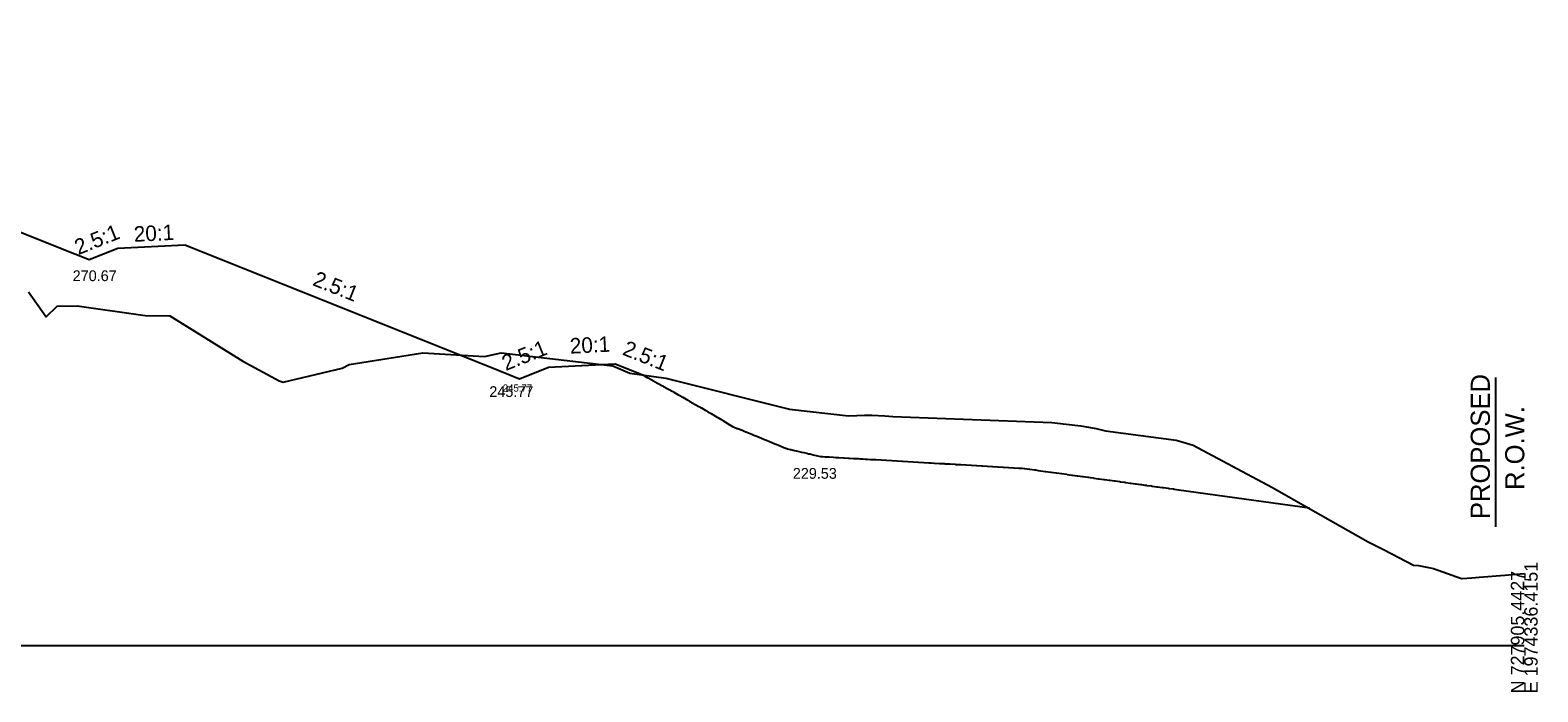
# Model space of a CAD drawing. Extents: x -26 to 1604, y -13 to 9623.
# Drawn here: x 287.7 to 602.8, y 7990.3 to 8128.6 of the extents above; entities that cross this region are included whole.
import ezdxf

# ---------------------------------------------------------------- set-up
doc = ezdxf.new("R2010")
doc.units = 0
for name, color, linetype in [('Default', 7, 'Continuous'), ('DTM CONTOURS_MAJOR', 7, 'Continuous'), ('DTM_X_GROUND', 7, 'Continuous'), ('SLOPE_STAKES_FILL', 7, 'Continuous'), ('XS_CELL', 7, 'Continuous'), ('XS_P_GROUND', 7, 'Continuous'), ('XS_P_ROW', 7, 'Continuous'), ('XS_P_TX_DCH', 7, 'Continuous'), ('XS_P_TX_FS_BS', 7, 'Continuous')]:
    doc.layers.add(name, color=color, linetype=linetype)

msp = doc.modelspace()

# ---------------------------------------------------------------- linework, layer by layer
at = {"layer": 'DTM_X_GROUND'}
msp.add_lwpolyline([(287.31, 8073.96), (291.04, 8068.73), (293.33, 8070.97), (297.48, 8071.01), (311.74, 8069), (316.85, 8068.91), (332.12, 8059.44), (339.7, 8055.36), (340.59, 8055.06), (352.88, 8058), (354.33, 8058.72), (369.76, 8061.16), (382.67, 8060.4), (386.12, 8061.2), (409.46, 8058.49), (413.06, 8056.92), (420.55, 8055.91), (446.41, 8049.38), (458.74, 8048.02), (460.47, 8048.07), (462.11, 8048.12), (463.65, 8048.17), (466.33, 8048.04), (467.98, 8047.87), (501.28, 8046.61), (504.23, 8046.28), (507.3, 8045.94), (510.52, 8045.36), (512.48, 8044.84), (527.24, 8042.93), (528.73, 8042.5), (530.82, 8041.91), (547.21, 8033.07), (557.38, 8027.32), (567.35, 8021.68), (570.73, 8019.99), (576.84, 8016.82), (577.91, 8016.74), (581.02, 8016.08), (586.91, 8013.97), (587.03, 8013.99), (589.06, 8014.17), (590.54, 8014.28), (595.97, 8014.73), (596.71, 8014.79), (600, 8015.02)], dxfattribs=at)
at = {"layer": 'XS_CELL'}
msp.add_line((100, 8000), (600, 8000), dxfattribs=at)
at = {"layer": 'XS_P_GROUND'}
for points in [[(142, 8128.64), (204, 8107.97), (210, 8105.97), (216, 8107.97), (230, 8108.67), (294, 8083.07), (300, 8080.67), (306, 8083.07), (320, 8083.77), (384, 8058.17), (390, 8055.77), (396, 8058.17), (410, 8058.87), (415.78, 8056.56)], [(415.78, 8056.56), (416.05, 8056.37), (416.06, 8056.37), (416.68, 8056.03), (416.71, 8056.01), (417.74, 8055.45), (417.82, 8055.4), (418.81, 8054.86), (418.93, 8054.79), (419.88, 8054.26), (420.04, 8054.17), (420.95, 8053.67), (421.15, 8053.55), (422.01, 8053.08), (422.26, 8052.93), (423.07, 8052.48), (423.37, 8052.3), (424.13, 8051.89), (424.48, 8051.68), (425.18, 8051.29), (425.59, 8051.04), (426.23, 8050.69), (426.71, 8050.41), (427.62, 8049.88), (427.82, 8049.77), (427.98, 8049.67), (427.99, 8049.67), (428.93, 8049.12), (429.37, 8048.87), (430.04, 8048.47), (430.4, 8048.27), (431.15, 8047.81), (431.43, 8047.65), (432.26, 8047.15), (432.45, 8047.04), (433.37, 8046.48), (433.47, 8046.42), (434.48, 8045.8), (434.48, 8045.8), (434.48, 8045.8), (435.47, 8045.39), (435.59, 8045.35), (436.48, 8044.99), (436.7, 8044.89), (437.49, 8044.57), (437.81, 8044.44), (437.82, 8044.44), (437.82, 8044.44), (438.52, 8044.15), (438.92, 8043.99), (439.55, 8043.74), (440.04, 8043.54), (440.56, 8043.33), (441.15, 8043.09), (441.57, 8042.91), (442.26, 8042.64), (442.58, 8042.5), (443.37, 8042.18), (443.6, 8042.09), (444.48, 8041.73), (444.61, 8041.68), (445.59, 8041.28), (445.62, 8041.27), (445.96, 8041.13)], [(445.96, 8041.13), (446.54, 8040.99), (446.7, 8040.96), (447.46, 8040.78), (447.81, 8040.7), (448.42, 8040.56), (448.92, 8040.44), (449.4, 8040.33), (450.03, 8040.18), (450.4, 8040.1), (450.65, 8040.04), (451.14, 8039.92), (451.38, 8039.87), (452.25, 8039.67), (452.86, 8039.53), (453.1, 8039.51), (453.36, 8039.5), (453.83, 8039.47), (454.48, 8039.43), (454.7, 8039.42), (455.59, 8039.37), (455.64, 8039.36), (456.14, 8039.33), (456.44, 8039.32), (456.45, 8039.32), (456.69, 8039.3), (456.7, 8039.3), (457.71, 8039.24), (457.81, 8039.24), (458.75, 8039.18), (458.92, 8039.17), (459.77, 8039.12), (460.03, 8039.11), (460.77, 8039.06), (461.14, 8039.04), (461.75, 8039.01), (462.25, 8038.98), (462.7, 8038.95), (463.36, 8038.91), (463.6, 8038.9), (464.34, 8038.85), (464.47, 8038.85), (464.47, 8038.85), (465.58, 8038.78), (465.59, 8038.78), (466.67, 8038.72), (466.67, 8038.72), (466.69, 8038.72), (466.71, 8038.72), (467.8, 8038.65), (467.82, 8038.65), (468.92, 8038.59), (468.94, 8038.59), (470.03, 8038.52), (470.06, 8038.52), (471.14, 8038.46), (471.17, 8038.46), (472.25, 8038.39), (472.28, 8038.39), (473.36, 8038.33), (473.4, 8038.33), (474.47, 8038.26), (475.54, 8038.2), (475.58, 8038.2), (476.02, 8038.17), (476.04, 8038.17), (476.66, 8038.13), (476.69, 8038.13), (477.75, 8038.07), (477.8, 8038.07), (478.86, 8038.01), (478.91, 8038), (479.97, 8037.94), (480.02, 8037.94), (481.08, 8037.88), (481.13, 8037.87), (482.19, 8037.81), (482.24, 8037.81), (483.29, 8037.75), (483.36, 8037.74), (484.4, 8037.68), (484.47, 8037.68), (485.51, 8037.62), (485.58, 8037.61), (486.62, 8037.55), (486.69, 8037.55), (486.76, 8037.54), (486.77, 8037.54), (487.73, 8037.49), (487.8, 8037.48), (488.83, 8037.42), (488.91, 8037.42), (489.94, 8037.36), (490.02, 8037.35), (491.05, 8037.29), (491.13, 8037.29), (492.16, 8037.23), (492.24, 8037.22), (493.27, 8037.17), (493.35, 8037.16), (494.37, 8037.1), (494.46, 8037.1), (495.02, 8037.06), (495.07, 8037.06), (495.53, 8037), (495.57, 8036.99), (496.59, 8036.85), (496.68, 8036.84), (497.7, 8036.7), (497.8, 8036.69), (498.38, 8036.61), (498.43, 8036.6), (498.86, 8036.54), (498.91, 8036.53), (499.92, 8036.39), (500.02, 8036.38), (501.02, 8036.24), (501.13, 8036.23), (502.13, 8036.09), (502.24, 8036.07), (503.24, 8035.94), (503.35, 8035.92), (504.35, 8035.78), (504.46, 8035.77), (505.46, 8035.63), (505.57, 8035.62), (506.56, 8035.48), (506.68, 8035.46), (507.67, 8035.33), (507.79, 8035.31), (508.78, 8035.18), (508.9, 8035.16), (509.23, 8035.11), (509.27, 8035.11), (509.93, 8035.02), (510.01, 8035.01), (511, 8034.87), (511.13, 8034.85), (512.1, 8034.72), (512.24, 8034.7), (513.21, 8034.57), (513.35, 8034.55), (514.32, 8034.41), (514.46, 8034.4), (515.43, 8034.26), (515.57, 8034.24), (516.53, 8034.11), (516.68, 8034.09), (517.64, 8033.96), (517.79, 8033.94), (518.75, 8033.81), (518.9, 8033.78), (519.86, 8033.65), (520.01, 8033.63), (520.71, 8033.54), (520.83, 8033.52), (521.08, 8033.49), (521.12, 8033.48), (522.07, 8033.35), (522.23, 8033.33), (523.18, 8033.2), (523.34, 8033.17), (524.29, 8033.04), (524.45, 8033.02), (524.62, 8033), (525.57, 8032.87), (525.74, 8032.85), (526.68, 8032.72), (526.85, 8032.69), (527.79, 8032.56), (555.13, 8028.81)]]:
    msp.add_lwpolyline(points, dxfattribs=at)
at = {"layer": 'XS_P_ROW'}
msp.add_line((594, 8056.05), (594, 8024.78), dxfattribs=at)

# ---------------------------------------------------------------- texts
at = {"layer": 'Default'}
msp.add_text('X', height=0.12, dxfattribs=at).set_placement((452.82, 8039.47))
at = {"layer": 'DTM CONTOURS_MAJOR'}
for p in [(434.44, 8045.74), (445.92, 8041.07), (445.92, 8041.07), (464.3, 8038.79)]:
    msp.add_text('X', height=0.12, dxfattribs=at).set_placement(p)
at = {"layer": 'SLOPE_STAKES_FILL'}
for p in [(293.96, 8083.01), (299.96, 8080.61), (305.96, 8083.01), (319.96, 8083.71), (409.96, 8058.81), (383.96, 8058.11), (389.96, 8055.71), (395.96, 8058.11)]:
    msp.add_text('X', height=0.12, dxfattribs=at).set_placement(p)
at = {"layer": 'XS_CELL'}
for s, p in [('N 727905.4427', (600, 7990)), ('E 1974336.4151', (602.8, 7990))]:
    msp.add_text(s, height=2.8, rotation=90, dxfattribs=at).set_placement(p)
at = {"layer": 'XS_P_GROUND'}
msp.add_text('X', height=0.12, dxfattribs=at).set_placement((415.74, 8056.5))
at = {"layer": 'XS_P_ROW'}
for s, p in [('PROPOSED', (592.81, 8026.43)), ('R.O.W.', (600.01, 8032.51))]:
    msp.add_text(s, height=4, rotation=90, dxfattribs=at).set_placement(p)
at = {"layer": 'XS_P_TX_DCH'}
for s, height, p in [('270.67', 2.25, (296.57, 8076.17)), ('245.77', 2.25, (383.66, 8051.95)), ('245.77', 1.5, (386.48, 8053.07)), ('229.53', 2.25, (447.1, 8034.85))]:
    msp.add_text(s, height=height, dxfattribs=at).set_placement(p)
at = {"layer": 'XS_P_TX_FS_BS'}
for s, rotation, p in [('2.5:1', 21.8014, (297.75, 8081.59)), ('20:1', 2.8624, (309.42, 8084.38)), ('2.5:1', 338.1986, (346.52, 8075.37)), ('2.5:1', 21.8014, (387.1, 8057.36)), ('20:1', 2.8624, (400.57, 8061)), ('2.5:1', 338.1986, (411.3, 8060.85))]:
    msp.add_text(s, height=3.24, rotation=rotation, dxfattribs=at).set_placement(p)

doc.saveas('drawing.dxf')
